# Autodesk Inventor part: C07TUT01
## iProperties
Created: 2009-04
Part Number: C07TUT01
Document SubType Name: Modeling
Designer: Sham
Density: 1 g/cm^3
Author: Sham
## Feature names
1. Extrusion1
2. Extrusion2
3. Extrusion3
4. Extrusion4
5. Extrusion5
6. Fillet1
7. Extrusion6
8. Extrusion7
